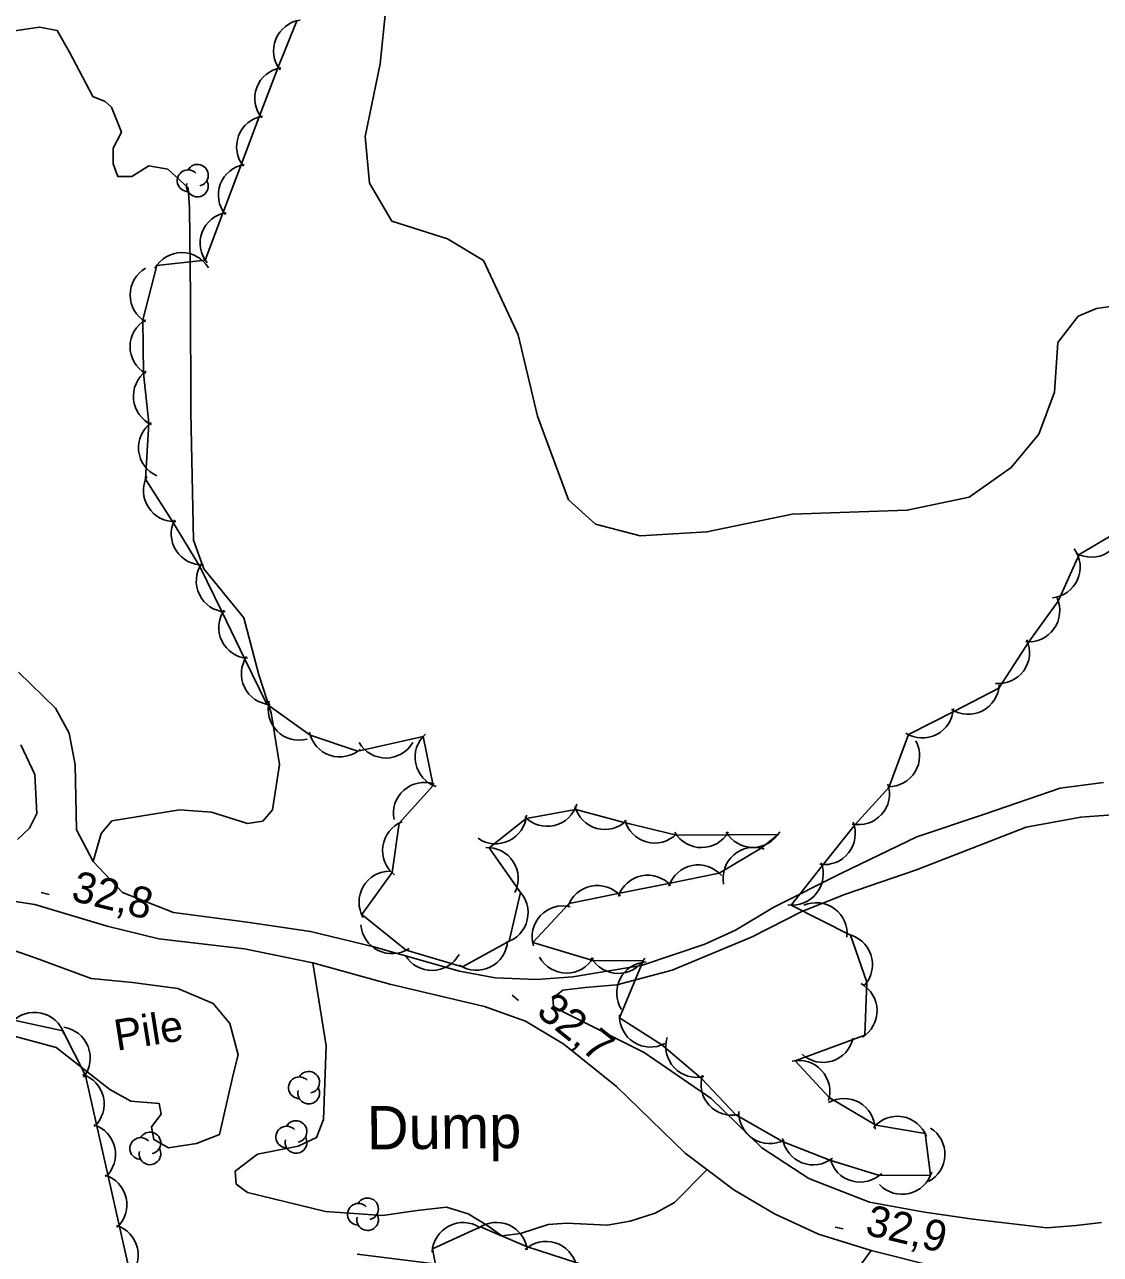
# Model space of a CAD drawing. Extents: x 646142 to 649934, y 5874075 to 5876351.
# Drawn here: x 648244.3 to 648348.6, y 5875856.5 to 5875975.7 of the extents above; entities that cross this region are included whole.
import ezdxf

# ---------------------------------------------------------------- set-up
doc = ezdxf.new("R2010")
doc.units = 0
for name, color, linetype in [('Niveau 2', 7, 'Continuous'), ('Niveau 21', 7, 'Continuous'), ('Niveau 22', 7, 'Continuous'), ('Niveau 3', 7, 'Continuous'), ('Niveau 44', 7, 'Continuous'), ('Niveau 57', 7, 'Continuous')]:
    doc.layers.add(name, color=color, linetype=linetype)

msp = doc.modelspace()

# ---------------------------------------------------------------- linework, layer by layer
at = {"layer": 'Niveau 2'}
for points in [[(648279.37, 5875977.28), (648278.81, 5875971.9), (648277.34, 5875964.84), (648277.79, 5875960.34), (648279.95, 5875956.65), (648285.34, 5875954.93), (648288.81, 5875952.84), (648292.2, 5875945.63), (648294.05, 5875937.74), (648297.06, 5875929.64), (648299.69, 5875927.26)], [(648342.65, 5875936.01), (648344.17, 5875940.08), (648344.5, 5875944.87), (648346.48, 5875947.43), (648348.25, 5875948.19), (648353.67, 5875948.95), (648355.28, 5875949.47), (648358.41, 5875954.18), (648359.87, 5875959.05), (648361.12, 5875960.69), (648363.77, 5875962.56), (648365.33, 5875964.63), (648368.86, 5875966.96), (648372.75, 5875972.18), (648375.1, 5875977.35)], [(648299.69, 5875927.26), (648304, 5875926.15), (648310.49, 5875926.52), (648318.75, 5875928.24), (648329.91, 5875928.62), (648335.92, 5875929.88), (648339.99, 5875932.77), (648342.65, 5875936.01)]]:
    msp.add_lwpolyline(points, dxfattribs=at)
at = {"layer": 'Niveau 21'}
for points in [[(648348.92, 5875902.22), (648344.74, 5875901.67), (648337.4, 5875899.17), (648330.84, 5875896.95), (648323.46, 5875893.41), (648316.97, 5875890.16), (648313.26, 5875887.93), (648310.28, 5875886.56), (648304.15, 5875884.48), (648300.21, 5875883.84), (648297.5, 5875883.4), (648293.98, 5875883.14), (648289.97, 5875883.29), (648286.5, 5875883.94), (648278.21, 5875886.3), (648272.04, 5875887.78), (648265.92, 5875888.69), (648258.76, 5875889.64), (648253.82, 5875891.56), (648250.97, 5875894.56), (648249.36, 5875897.65), (648249.23, 5875903.95), (648248.66, 5875907.01), (648247.34, 5875909.43), (648243.76, 5875912.94)], [(648243.65, 5875896.69), (648244.82, 5875897.81), (648245.51, 5875899.24), (648245.34, 5875903.01), (648243.98, 5875905.89)], [(648349.79, 5875899.1), (648346.73, 5875898.87), (648341.45, 5875897.89), (648330.81, 5875893.76), (648323.91, 5875891.4), (648319.7, 5875889.71), (648314.86, 5875887.27), (648307.12, 5875884.05), (648301.74, 5875882.6), (648298.68, 5875882.37), (648296.53, 5875882.09), (648295.56, 5875881.33), (648295.62, 5875880.53), (648296.69, 5875879.93), (648304.4, 5875876.04), (648310.9, 5875871.6), (648315.82, 5875866.81), (648320.38, 5875863.84), (648326.26, 5875861.53), (648331.58, 5875860.56), (648336.3, 5875859.91)], [(648243.01, 5875890.77), (648245.34, 5875890.4), (648252.35, 5875888.29), (648257.36, 5875887.07), (648265.66, 5875886.09), (648272.27, 5875884.76), (648279.74, 5875882.68), (648288.92, 5875880.51), (648292.91, 5875879.1), (648296.62, 5875876.85), (648301.72, 5875872.77), (648308.37, 5875866.28), (648313.09, 5875862.74)], [(648313.09, 5875862.74), (648317.03, 5875860.4), (648321.29, 5875858.43), (648326.42, 5875856.87), (648332.7, 5875855.29)], [(648336.3, 5875859.91), (648343.43, 5875859.07), (648346.27, 5875859.29), (648348.75, 5875859.59)]]:
    msp.add_lwpolyline(points, dxfattribs=at)
at = {"layer": 'Niveau 22'}
msp.add_lwpolyline([(648326.42, 5875856.87), (648324.46, 5875854.2), (648321.99, 5875850.57), (648319.44, 5875848.08), (648317.11, 5875847.22), (648314.98, 5875846.6), (648312.81, 5875846.66), (648309.49, 5875846.86), (648302.85, 5875848.65), (648299.52, 5875850.46), (648296.03, 5875852.94), (648293.57, 5875853.79), (648289.72, 5875854.87), (648276.58, 5875856.5)], dxfattribs=at)
at = {"layer": 'Niveau 3'}
for p, q in [((648245.96, 5875891.56), (648246.73, 5875891.36)), ((648291.61, 5875881.61), (648292.23, 5875881.11)), ((648322.93, 5875859.13), (648323.7, 5875858.95))]:
    msp.add_line(p, q, dxfattribs=at)
at = {"layer": 'Niveau 44'}
for points in [[(648270.74, 5875976.08), (648268.92, 5875971.58), (648267.09, 5875966.76), (648265.38, 5875962.22), (648263.56, 5875957.41), (648261.85, 5875952.87), (648257.15, 5875952.35), (648255.8, 5875947.07), (648255.87, 5875941.9), (648256.37, 5875937.07), (648256.06, 5875931.63), (648258.68, 5875927.54), (648261.33, 5875923.17), (648263.45, 5875918.81), (648265.7, 5875914.18), (648267.83, 5875909.81), (648272.03, 5875906.81)], [(648272.03, 5875906.81), (648276.63, 5875905.26), (648282.97, 5875906.7), (648283.96, 5875901.95), (648280.64, 5875898.29), (648279.97, 5875893.49), (648277.02, 5875889.42), (648281.34, 5875885.98), (648286.78, 5875884.36), (648291.32, 5875886.84), (648292.42, 5875891.57), (648289.36, 5875895.91), (648292.95, 5875898.74), (648297.79, 5875899.61), (648302.47, 5875898.34), (648307.53, 5875897.14), (648312.38, 5875897.17), (648317.38, 5875897.19), (648315.73, 5875895.87), (648311.68, 5875893.45), (648306.92, 5875892.48), (648301.88, 5875891.46), (648297.12, 5875890.49), (648293.6, 5875886.71), (648299.43, 5875884.97), (648304.29, 5875884.93), (648302.02, 5875879.4), (648306.11, 5875876.79), (648309.97, 5875873.55), (648313.28, 5875870), (648317.88, 5875867.4), (648322.4, 5875865.63), (648327.2, 5875864.13), (648332.17, 5875864.17), (648331.64, 5875868.21), (648326.85, 5875869.01), (648322.34, 5875871.69), (648319.05, 5875875.26), (648325.79, 5875877.72), (648326, 5875882.86), (648324.41, 5875887.44), (648318.65, 5875890.35), (648321.66, 5875894.16), (648324.87, 5875898.16), (648328.11, 5875901.76), (648330.03, 5875906.87), (648334.48, 5875909.16), (648338.79, 5875911.39), (648341.7, 5875915.87), (648344.54, 5875919.81), (648346.57, 5875924.32), (648350.74, 5875926.8)], [(648254.63, 5875854.31), (648253.5, 5875859.33), (648252.43, 5875864.07), (648251.3, 5875869.09), (648250.24, 5875873.82), (648248.04, 5875878.17), (648243.29, 5875879.19)], [(648284.2, 5875855.33), (648287, 5875851.37), (648290, 5875847.17), (648292.92, 5875843.3), (648295.68, 5875838.98), (648298.26, 5875834.87), (648301.12, 5875830.46), (648303.58, 5875828.31), (648308.16, 5875826.04), (648312.64, 5875824.17), (648317.7, 5875823.84), (648319.08, 5875824.1), (648319.46, 5875829.22), (648317.32, 5875833.57), (648314.7, 5875838.03), (648311.89, 5875841.99), (648308.98, 5875846.27), (648305.79, 5875849.93), (648302.51, 5875854.22), (648297.87, 5875855.66), (648293.01, 5875857.24), (648288.55, 5875859.16), (648283.88, 5875857.02), (648284.2, 5875855.33)]]:
    msp.add_lwpolyline(points, dxfattribs=at)
for centre, radius, start, end in [((648271.47, 5875973.17), 3, 98.0575, 218.0354), ((648269.65, 5875968.55), 3, 99.3355, 219.3134), ((648267.89, 5875963.87), 3, 99.3355, 219.3134), ((648260.19, 5875960.57), 1.05, 44.1154, 269.804), ((648261.09, 5875961.1), 1.05, 282.2692, 149.7263), ((648266.12, 5875959.19), 3, 99.3355, 219.3134), ((648261.09, 5875960.05), 1.05, 166.9369, 29.6212), ((648264.35, 5875954.51), 3, 99.3355, 219.3134), ((648259.58, 5875950.6), 3, 30.2209, 150.1989), ((648257.57, 5875949.49), 3, 119.9374, 239.9154), ((648257.56, 5875944.49), 3, 119.9374, 239.9154), ((648257.88, 5875939.66), 3, 125.8572, 245.8351), ((648258.38, 5875934.69), 3, 125.8572, 245.8351), ((648258.86, 5875930.53), 3, 152.6869, 272.6648), ((648261.55, 5875926.33), 3, 152.6869, 272.6648), ((648347.76, 5875927.07), 3, 240.7029, 0.6808), ((648343.67, 5875923.11), 3, 276.0016, 35.9795), ((648263.98, 5875921.76), 3, 145.9475, 265.9255), ((648341.69, 5875918.87), 3, 264.1952, 24.1732), ((648266.16, 5875917.26), 3, 145.9475, 265.9255), ((648338.76, 5875914.82), 3, 264.1952, 24.1732), ((648268.35, 5875912.77), 3, 145.9475, 265.9255), ((648335.82, 5875911.84), 3, 237.2892, 357.2672), ((648270.95, 5875909.33), 3, 164.8431, 284.821), ((648331.38, 5875909.55), 3, 237.2892, 357.2672), ((648274.9, 5875907.71), 3, 191.3626, 311.3406), ((648285.19, 5875904.68), 3, 131.7104, 251.6883), ((648279.38, 5875907.6), 3, 210.0986, 330.0765), ((648328.1, 5875904.82), 3, 268.8103, 28.7882), ((648283.09, 5875899.24), 3, 71.6562, 191.6341), ((648325.18, 5875901.14), 3, 258.0247, 18.0027), ((648295, 5875900.98), 3, 223.6487, 343.6266), ((648300.59, 5875900.68), 3, 194.7901, 314.768), ((648282.05, 5875895.64), 3, 111.9916, 231.9695), ((648290, 5875899.29), 3, 235.4836, 355.4615), ((648305.42, 5875899.36), 3, 194.7901, 314.768), ((648321.87, 5875897.27), 3, 261.6818, 21.6598), ((648309.95, 5875898.92), 3, 210.3133, 330.2912), ((648314.95, 5875898.94), 3, 210.3133, 330.2912), ((648289.2, 5875892.92), 3, 332.9489, 92.9268), ((648315.05, 5875892.94), 3, 71.0107, 190.9887), ((648279.76, 5875890.63), 3, 89.76, 209.7379), ((648309.65, 5875891.24), 3, 41.5246, 161.5026), ((648318.77, 5875893.35), 3, 261.6818, 21.6598), ((648299.85, 5875889.25), 3, 41.5246, 161.5026), ((648304.75, 5875890.24), 3, 41.5246, 161.5026), ((648290.15, 5875889.6), 3, 286.8694, 46.8474), ((648296.54, 5875887.27), 3, 76.8758, 196.8537), ((648321.08, 5875887.58), 3, 353.5972, 113.5752), ((648279.94, 5875888.64), 3, 183.7073, 303.6852), ((648323.54, 5875884.57), 3, 319.1706, 79.1486), ((648288.16, 5875887.03), 3, 236.7039, 356.6819), ((648283.83, 5875887.01), 3, 210.9182, 330.8961), ((648296.88, 5875886.76), 3, 209.516, 329.494), ((648301.88, 5875886.72), 3, 209.516, 329.494), ((648304.74, 5875881.84), 3, 92.8436, 212.8216), ((648323.98, 5875880.11), 3, 301.0539, 61.0319), ((648245.3, 5875876.95), 3, 17.8771, 137.855), ((648305.01, 5875879.58), 3, 177.5615, 297.5394), ((648247.7, 5875875.53), 3, 321.6803, 81.6582), ((648309.5, 5875876.64), 3, 163.0112, 282.9891), ((648321.73, 5875878.09), 3, 227.4994, 347.4774), ((648319.4, 5875872.28), 3, 342.7285, 102.7064), ((648249.05, 5875871.07), 3, 312.7076, 72.6856), ((648270.98, 5875872.64), 1.05, 44.1154, 269.804), ((648271.88, 5875873.17), 1.05, 282.2692, 149.7263), ((648312.91, 5875872.98), 3, 163.0112, 282.9891), ((648271.88, 5875872.12), 1.05, 166.9369, 29.6212), ((648323.78, 5875868.6), 3, 0.1454, 120.1234), ((648316.58, 5875870.22), 3, 177.585, 297.563), ((648328.95, 5875866.87), 3, 20.5274, 140.5053), ((648250.15, 5875866.19), 3, 312.7076, 72.6856), ((648269.75, 5875867.86), 1.05, 44.1154, 269.804), ((648270.65, 5875868.39), 1.05, 282.2692, 149.7263), ((648330.56, 5875866.19), 3, 297.8803, 57.8583), ((648255.59, 5875866.75), 1.05, 44.1154, 269.804), ((648256.49, 5875867.28), 1.05, 282.2692, 149.7263), ((648270.65, 5875867.34), 1.05, 166.9369, 29.6212), ((648320.79, 5875868.16), 3, 188.5789, 308.5569), ((648256.49, 5875866.23), 1.05, 166.9369, 29.6212), ((648325.34, 5875866.49), 3, 194.1095, 314.0874), ((648251.25, 5875861.31), 3, 312.7076, 72.6856), ((648329.4, 5875865.31), 3, 223.5175, 343.4955), ((648276.69, 5875860.37), 1.05, 44.1154, 269.804), ((648277.59, 5875860.9), 1.05, 282.2692, 149.7263), ((648277.59, 5875859.85), 1.05, 166.9369, 29.6212), ((648252.35, 5875856.43), 3, 312.7076, 72.6856), ((648286.85, 5875856.57), 3, 57.4011, 177.3791), ((648290.08, 5875856.58), 3, 6.6628, 126.6408), ((648294.89, 5875854.74), 3, 12.762, 132.74)]:
    msp.add_arc(centre, radius, start, end, dxfattribs=at)
at = {"layer": 'Niveau 57'}
for points in [[(648242.72, 5875974.99), (648245.77, 5875975.45), (648247.51, 5875975.12), (648248.69, 5875973.03), (648250.96, 5875968.72), (648252.14, 5875968.24), (648252.75, 5875967.71), (648253.73, 5875965.26), (648252.93, 5875963.71), (648252.93, 5875962.22), (648253.37, 5875960.99), (648254.74, 5875960.98), (648256.37, 5875962.02), (648258.22, 5875961.7), (648260.19, 5875959.89), (648260.33, 5875957.95), (648260.41, 5875949.35), (648260.45, 5875938.1), (648260.7, 5875925.72), (648261.7, 5875922.93), (648265.6, 5875918.18), (648267.04, 5875912.67), (648268.23, 5875908.97), (648269.06, 5875903.99), (648268.37, 5875899.58), (648267.42, 5875898.48), (648265.96, 5875898.25), (648262.45, 5875899.36), (648259.35, 5875899.58), (648252.8, 5875898.51), (648251.75, 5875897.29), (648250.97, 5875894.56)], [(648241.61, 5875886.54), (648245.37, 5875885.22), (648250.78, 5875883.22), (648254.8, 5875882.84), (648259.19, 5875882.26), (648262.61, 5875880.79), (648264.24, 5875878.85), (648265.04, 5875875.82), (648264.6, 5875874.06), (648263.22, 5875868.1), (648261, 5875867.24), (648258.29, 5875866.81), (648256.86, 5875867.62), (648256.65, 5875868.86), (648257.59, 5875870.08), (648257.4, 5875871.1), (648254.64, 5875871.35), (648252.61, 5875872.46), (648247.39, 5875876.54), (648242.14, 5875877.97), (648237.65, 5875878.43), (648235.51, 5875880.02)], [(648295.09, 5875859.39), (648292.4, 5875858.52), (648290.59, 5875858.27), (648289.15, 5875859.3), (648287.35, 5875860.43), (648285.24, 5875861.07), (648282.41, 5875860.74), (648279.02, 5875860.25), (648273.51, 5875860.63), (648265.95, 5875862.47), (648264.86, 5875863.3), (648264.76, 5875864.56), (648266.92, 5875866.21), (648270.86, 5875866.97), (648272.63, 5875867.8), (648273.3, 5875869.57), (648273.56, 5875876.7), (648272.27, 5875884.76)], [(648295.09, 5875859.39), (648296.89, 5875859.5), (648298.86, 5875859.4), (648300.8, 5875859.32), (648303.05, 5875859.71), (648305.48, 5875860.49), (648307.33, 5875861.52), (648310.49, 5875864.69)]]:
    msp.add_lwpolyline(points, dxfattribs=at)

# ---------------------------------------------------------------- texts
at = {"layer": 'Niveau 3'}
for s, rotation, p in [('32,8 ', 345.915, (648248.74, 5875890.82)), ('32,7 ', 321.2567, (648293.83, 5875879.78)), ('32,9 ', 346.6118, (648325.72, 5875858.43))]:
    msp.add_text(s, height=3, rotation=rotation, dxfattribs=at).set_placement(p)
at = {"layer": 'Niveau 57'}
for s, height, rotation, p in [('Pile', 3, 8.9405, (648253.27, 5875876.22)), ('Dump', 4.2, 0.5571, (648277.53, 5875866.65))]:
    msp.add_text(s, height=height, rotation=rotation, dxfattribs=at).set_placement(p)

doc.saveas('drawing.dxf')
